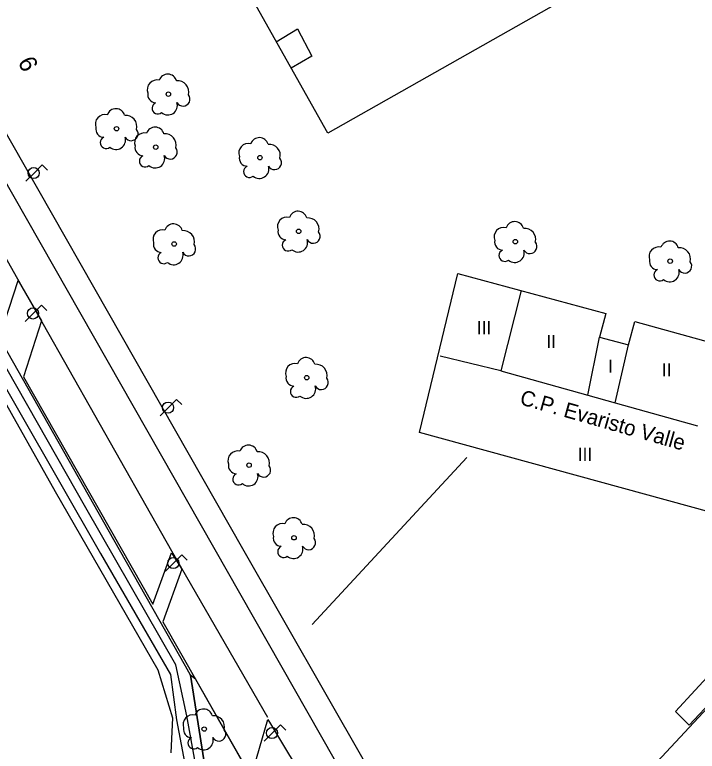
# Model space of a CAD drawing. Extents: x 282771 to 285132, y 4823109 to 4825496.
# Drawn here: x 283559 to 283637.2, y 4823197.1 to 4823281.4 of the extents above; entities that cross this region are included whole.
import ezdxf

# ---------------------------------------------------------------- set-up
doc = ezdxf.new("R2010")
doc.units = 0
for name, color, linetype in [('ACERA-BORDILLO', 7, 'Continuous'), ('ACERA-INTERIOR', 7, 'Continuous'), ('ARBOL', 7, 'Continuous'), ('CALLE-EJE', 7, 'Continuous'), ('CARRIL-BICI-AREA', 7, 'Continuous'), ('CARRIL-BICI-EJE', 7, 'Continuous'), ('COLEGIO-AREA', 7, 'Continuous'), ('COLEGIO-TEXTO', 7, 'Continuous'), ('EDIFICIO', 7, 'Continuous'), ('FAROLA', 7, 'Continuous'), ('MEDIANERA', 7, 'Continuous'), ('NUM-PORTAL', 7, 'Continuous'), ('SENAL-VIARIA', 7, 'Continuous'), ('TXT-ALTURA-EDIFICIO', 7, 'Continuous'), ('ZONA-VERDE', 7, 'Continuous')]:
    doc.layers.add(name, color=color, linetype=linetype)

msp = doc.modelspace()

# ---------------------------------------------------------------- linework, layer by layer
at = {"layer": 'ACERA-BORDILLO'}
for points in [[(283599.222, 4823195.624), (283585.304, 4823219.992), (283546.134, 4823288.772)], [(283557.324, 4823244.642), (283559.404, 4823251.012), (283562.074, 4823246.362), (283560.034, 4823239.962), (283574.844, 4823213.912), (283576.984, 4823219.782), (283578.154, 4823217.942), (283575.984, 4823211.912), (283586.104, 4823194.133), (283588.014, 4823200.723), (283588.294, 4823200.203), (283592.738, 4823192.856), (283596.176, 4823192.9), (283598.164, 4823189.61), (283603.144, 4823181.987), (283607.264, 4823176.035), (283616.731, 4823162.949), (283619.11, 4823159.533), (283619.358, 4823153.99), (283630.204, 4823141.713), (283654.443, 4823115.363)], [(283651.523, 4823216.182), (283629.944, 4823193.013)]]:
    msp.add_lwpolyline(points, dxfattribs=at)
at = {"layer": 'ACERA-INTERIOR'}
msp.add_lwpolyline([(283610.77, 4823230.716), (283593.091, 4823211.57)], dxfattribs=at)
at = {"layer": 'ARBOL'}
for centre in [(283576.613, 4823272.339), (283570.673, 4823268.38), (283575.161, 4823266.268), (283587.094, 4823265.062), (283591.527, 4823256.633), (283577.273, 4823255.181), (283616.341, 4823255.445), (283634.073, 4823253.212), (283592.451, 4823239.87), (283585.852, 4823229.839), (283590.999, 4823221.524), (283580.713, 4823199.607)]:
    msp.add_circle(centre, 0.255, dxfattribs=at)
for centre, radius, start, end in [((283576.543, 4823273.599), 1.038, 15.64228, 161.38435), ((283575.283, 4823272.869), 1.097, 75.4318, 200.55608), ((283577.673, 4823272.599), 1.272, 345.03273, 95.79925), ((283575.173, 4823272.299), 0.935, 168.59898, 268.13236), ((283578.283, 4823271.769), 0.797, 208.96246, 38.99103), ((283570.603, 4823269.64), 1.038, 15.64228, 161.38435), ((283575.413, 4823270.749), 0.672, 113.73672, 309.4725), ((283576.553, 4823271.049), 1.086, 228.95447, 17.92796), ((283569.343, 4823268.91), 1.097, 75.4318, 200.55608), ((283571.733, 4823268.64), 1.272, 345.03273, 95.79925), ((283569.233, 4823268.34), 0.935, 168.59898, 268.13236), ((283572.343, 4823267.81), 0.797, 208.96246, 38.99103), ((283575.091, 4823267.528), 1.038, 15.64228, 161.38435), ((283569.473, 4823266.79), 0.672, 113.73672, 309.4725), ((283570.613, 4823267.09), 1.086, 228.95447, 17.92796), ((283573.831, 4823266.798), 1.097, 75.4318, 200.55608), ((283576.221, 4823266.528), 1.272, 345.03273, 95.79925), ((283587.024, 4823266.322), 1.038, 15.64228, 161.38435), ((283573.721, 4823266.228), 0.935, 168.59898, 268.13236), ((283585.764, 4823265.592), 1.097, 75.4318, 200.55608), ((283588.154, 4823265.322), 1.272, 345.03273, 95.79925), ((283576.831, 4823265.698), 0.797, 208.96246, 38.99103), ((283573.961, 4823264.678), 0.672, 113.73672, 309.4725), ((283575.101, 4823264.978), 1.086, 228.95447, 17.92796), ((283585.654, 4823265.022), 0.935, 168.59898, 268.13236), ((283588.764, 4823264.492), 0.797, 208.96246, 38.99103), ((283585.894, 4823263.472), 0.672, 113.73672, 309.4725), ((283587.034, 4823263.772), 1.086, 228.95447, 17.92796), ((283591.457, 4823257.893), 1.038, 15.64228, 161.38435), ((283590.197, 4823257.163), 1.097, 75.4318, 200.55608), ((283592.587, 4823256.893), 1.272, 345.03273, 95.79925), ((283577.203, 4823256.441), 1.038, 15.64228, 161.38435), ((283616.271, 4823256.705), 1.038, 15.64228, 161.38435), ((283575.943, 4823255.711), 1.097, 75.4318, 200.55608), ((283578.333, 4823255.441), 1.272, 345.03273, 95.79925), ((283590.087, 4823256.593), 0.935, 168.59898, 268.13236), ((283593.197, 4823256.063), 0.797, 208.96246, 38.99103), ((283615.011, 4823255.975), 1.097, 75.4318, 200.55608), ((283617.401, 4823255.705), 1.272, 345.03273, 95.79925), ((283590.327, 4823255.043), 0.672, 113.73672, 309.4725), ((283591.467, 4823255.343), 1.086, 228.95447, 17.92796), ((283614.901, 4823255.405), 0.935, 168.59898, 268.13236), ((283634.003, 4823254.472), 1.038, 15.64228, 161.38435), ((283575.833, 4823255.141), 0.935, 168.59898, 268.13236), ((283578.943, 4823254.611), 0.797, 208.96246, 38.99103), ((283618.011, 4823254.875), 0.797, 208.96246, 38.99103), ((283632.743, 4823253.742), 1.097, 75.4318, 200.55608), ((283635.133, 4823253.472), 1.272, 345.03273, 95.79925), ((283576.073, 4823253.591), 0.672, 113.73672, 309.4725), ((283577.213, 4823253.891), 1.086, 228.95447, 17.92796), ((283615.141, 4823253.855), 0.672, 113.73672, 309.4725), ((283616.281, 4823254.155), 1.086, 228.95447, 17.92796), ((283632.633, 4823253.172), 0.935, 168.59898, 268.13236), ((283635.743, 4823252.642), 0.797, 208.96246, 38.99103), ((283632.873, 4823251.622), 0.672, 113.73672, 309.4725), ((283634.013, 4823251.922), 1.086, 228.95447, 17.92796), ((283592.381, 4823241.13), 1.038, 15.64228, 161.38435), ((283591.121, 4823240.4), 1.097, 75.4318, 200.55608), ((283593.511, 4823240.13), 1.272, 345.03273, 95.79925), ((283591.011, 4823239.83), 0.935, 168.59898, 268.13236), ((283594.121, 4823239.3), 0.797, 208.96246, 38.99103), ((283591.251, 4823238.28), 0.672, 113.73672, 309.4725), ((283592.391, 4823238.58), 1.086, 228.95447, 17.92796), ((283585.782, 4823231.099), 1.038, 15.64228, 161.38435), ((283584.522, 4823230.369), 1.097, 75.4318, 200.55608), ((283586.912, 4823230.099), 1.272, 345.03273, 95.79925), ((283584.412, 4823229.799), 0.935, 168.59898, 268.13236), ((283587.522, 4823229.269), 0.797, 208.96246, 38.99103), ((283584.652, 4823228.249), 0.672, 113.73672, 309.4725), ((283585.792, 4823228.549), 1.086, 228.95447, 17.92796), ((283590.929, 4823222.784), 1.038, 15.64228, 161.38435), ((283589.669, 4823222.054), 1.097, 75.4318, 200.55608), ((283592.059, 4823221.784), 1.272, 345.03273, 95.79925), ((283589.559, 4823221.484), 0.935, 168.59898, 268.13236), ((283592.669, 4823220.954), 0.797, 208.96246, 38.99103), ((283589.799, 4823219.934), 0.672, 113.73672, 309.4725), ((283590.939, 4823220.234), 1.086, 228.95447, 17.92796), ((283580.643, 4823200.867), 1.038, 15.64225, 161.38431), ((283579.383, 4823200.137), 1.097, 75.43176, 200.55605), ((283581.773, 4823199.867), 1.272, 345.0327, 95.79922), ((283579.273, 4823199.567), 0.935, 168.59894, 268.13232), ((283582.383, 4823199.037), 0.797, 208.96243, 38.99099), ((283579.513, 4823198.017), 0.672, 113.73669, 309.47246), ((283580.653, 4823198.317), 1.086, 228.95444, 17.92792)]:
    msp.add_arc(centre, radius, start, end, dxfattribs=at)
at = {"layer": 'CALLE-EJE'}
msp.add_lwpolyline([(283614.194, 4823170.773), (283603.264, 4823182.723), (283539.034, 4823295.561), (283497.955, 4823367.291), (283418.753, 4823502.18), (283376.815, 4823559.518)], dxfattribs=at)
at = {"layer": 'CARRIL-BICI-AREA'}
for points in [[(283586.315, 4823175.064), (283585.109, 4823178.511), (283583.571, 4823184.071), (283581.75, 4823191.39), (283580.683, 4823196.079), (283579.144, 4823205.776), (283578.559, 4823206.816), (283570.351, 4823221.278), (283557.07, 4823244.688), (283542.273, 4823270.673), (283514.226, 4823320.281)], [(283513.047, 4823317.608), (283540.681, 4823269.002), (283554.699, 4823244.343), (283568.839, 4823219.741), (283576.866, 4823205.852), (283577.543, 4823200.656), (283579.427, 4823190.793), (283581.311, 4823183.16), (283583.006, 4823177.254), (283584.338, 4823173.515), (283586.315, 4823175.064)]]:
    msp.add_lwpolyline(points, dxfattribs=at)
at = {"layer": 'CARRIL-BICI-EJE'}
msp.add_lwpolyline([(283441.214, 4823143.708), (283523.993, 4823131.455), (283531.751, 4823130.709), (283535.641, 4823131.245), (283537.075, 4823132.46), (283548.321, 4823142.602), (283564.588, 4823156.236), (283589.666, 4823176.835), (283610.049, 4823155.788), (283605.959, 4823151.91), (283587.866, 4823170.996), (283585.856, 4823173.584), (283583.97, 4823177.522), (283581.141, 4823188.354), (283579.747, 4823195.452), (283578.716, 4823201.119), (283577.48, 4823206.952), (283567.144, 4823224.963), (283513.379, 4823319.553)], dxfattribs=at)
at = {"layer": 'COLEGIO-AREA'}
for points in [[(283643.713, 4823295.562), (283594.884, 4823267.882), (283586.328, 4823283.056), (283598.434, 4823289.912), (283607.724, 4823295.561), (283610.164, 4823297.042), (283634.083, 4823310.251), (283649.233, 4823319.561), (283650.343, 4823320.191), (283655.313, 4823311.182), (283643.713, 4823304.311), (283647.473, 4823297.692)], [(283641.434, 4823223.702), (283605.366, 4823233.602), (283609.762, 4823251.781), (283626.714, 4823247.232), (283625.984, 4823244.522), (283629.304, 4823243.622), (283630.033, 4823246.282), (283646.437, 4823241.767)]]:
    msp.add_lwpolyline(points, close=True, dxfattribs=at)
at = {"layer": 'EDIFICIO'}
for points in [[(283643.713, 4823295.562), (283594.884, 4823267.882), (283586.328, 4823283.056), (283598.434, 4823289.912), (283607.724, 4823295.562), (283610.164, 4823297.042), (283634.083, 4823310.251), (283650.383, 4823320.211), (283655.313, 4823311.181), (283643.713, 4823304.311), (283647.473, 4823297.692), (283643.713, 4823295.562)], [(283609.762, 4823251.781), (283626.714, 4823247.232), (283625.984, 4823244.522), (283629.304, 4823243.622), (283630.033, 4823246.282), (283646.437, 4823241.767), (283641.433, 4823223.702), (283605.366, 4823233.602), (283609.762, 4823251.781)]]:
    msp.add_lwpolyline(points, dxfattribs=at)
at = {"layer": 'FAROLA'}
for p, q in [((283562.166, 4823264.233), (283561.226, 4823263.303)), ((283562.756, 4823263.643), (283562.166, 4823264.233)), ((283561.226, 4823263.303), (283560.296, 4823262.363)), ((283562.084, 4823248.152), (283561.144, 4823247.222)), ((283562.674, 4823247.562), (283562.084, 4823248.152)), ((283561.144, 4823247.222), (283560.214, 4823246.282)), ((283577.556, 4823237.366), (283576.616, 4823236.436)), ((283578.146, 4823236.776), (283577.556, 4823237.366)), ((283576.616, 4823236.436), (283575.686, 4823235.496)), ((283578.154, 4823219.552), (283577.214, 4823218.622)), ((283578.744, 4823218.962), (283578.154, 4823219.552)), ((283577.214, 4823218.622), (283576.284, 4823217.682)), ((283589.452, 4823200.079), (283588.512, 4823199.149)), ((283590.042, 4823199.489), (283589.452, 4823200.079)), ((283588.512, 4823199.149), (283587.582, 4823198.209))]:
    msp.add_line(p, q, dxfattribs=at)
for centre, radius in [((283561.186, 4823263.303), 0.638), ((283561.104, 4823247.222), 0.637), ((283576.576, 4823236.436), 0.638), ((283577.174, 4823218.622), 0.637), ((283588.472, 4823199.149), 0.637)]:
    msp.add_circle(centre, radius, dxfattribs=at)
at = {"layer": 'MEDIANERA'}
for points in [[(283588.944, 4823278.342), (283591.384, 4823279.812), (283593.054, 4823276.692), (283590.684, 4823275.322)], [(283617.024, 4823249.832), (283614.674, 4823240.642)], [(283624.644, 4823237.852), (283625.984, 4823244.522)], [(283627.764, 4823236.982), (283629.304, 4823243.622)], [(283614.674, 4823240.642), (283607.714, 4823242.312)], [(283614.674, 4823240.642), (283624.644, 4823237.852)], [(283624.644, 4823237.852), (283627.764, 4823236.982)], [(283627.764, 4823236.982), (283637.183, 4823234.362)]]:
    msp.add_lwpolyline(points, dxfattribs=at)
at = {"layer": 'SENAL-VIARIA'}
msp.add_lwpolyline([(283516.389, 4823327.217), (283544.224, 4823277.952), (283559.324, 4823251.172), (283576.954, 4823220.032), (283587.964, 4823200.982)], dxfattribs=at)
at = {"layer": 'ZONA-VERDE'}
for p, q in [((283537.718, 4823272.86), (283563.647, 4823226.823)), ((283563.647, 4823226.823), (283575.395, 4823206.397)), ((283634.673, 4823201.637), (283654.65, 4823223.338)), ((283656.38, 4823221.68), (283636.257, 4823200.052)), ((283575.395, 4823206.397), (283577.088, 4823200.893)), ((283579.755, 4823205.288), (283579.144, 4823205.776)), ((283586.104, 4823194.133), (283579.755, 4823205.288)), ((283636.257, 4823200.052), (283634.673, 4823201.637)), ((283577.088, 4823200.893), (283576.876, 4823196.872))]:
    msp.add_line(p, q, dxfattribs=at)
msp.add_lwpolyline([(283579.144, 4823205.776), (283580.683, 4823196.079), (283581.75, 4823191.39), (283583.571, 4823184.071), (283585.109, 4823178.511), (283586.22, 4823175.335)], dxfattribs=at)

# ---------------------------------------------------------------- texts
at = {"layer": 'COLEGIO-TEXTO'}
msp.add_text('C.P. Evaristo Valle', height=1.75, rotation=344.11767, dxfattribs=at).set_placement((283616.746, 4823236.838))
at = {"layer": 'NUM-PORTAL'}
msp.add_text('6', height=2, rotation=295.73004, dxfattribs=at).set_placement((283559.336, 4823276.057))
at = {"layer": 'TXT-ALTURA-EDIFICIO'}
for s, p in [('III', (283611.918, 4823244.838)), ('II', (283619.888, 4823243.25)), ('I', (283626.942, 4823240.442)), ('II', (283633.115, 4823240.008)), ('III', (283623.482, 4823230.332))]:
    msp.add_text(s, height=1.5, rotation=0.00004, dxfattribs=at).set_placement(p)

doc.saveas('drawing.dxf')
